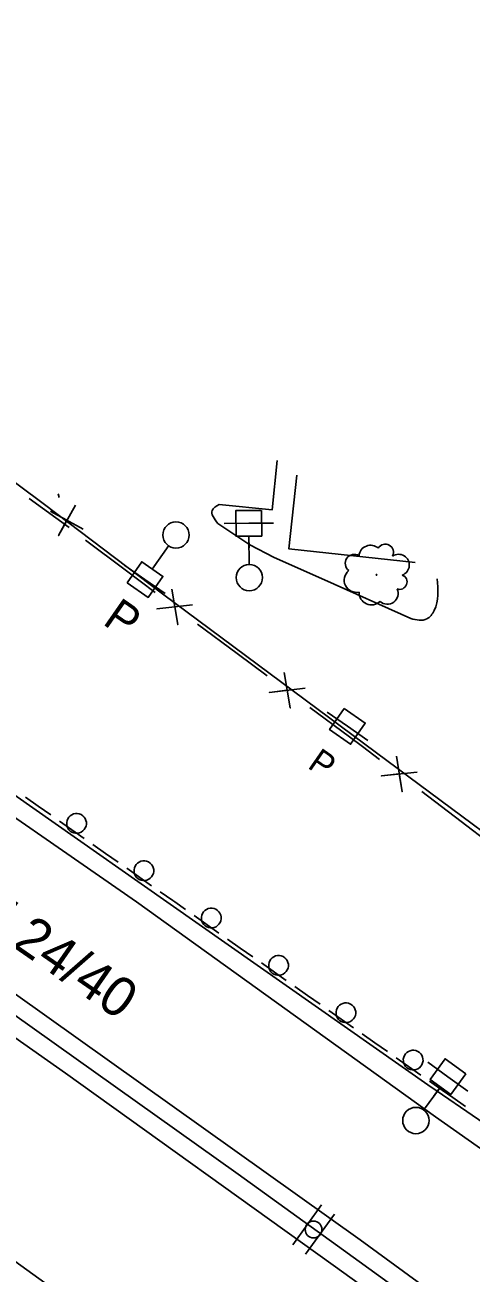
# Model space of a CAD drawing. Extents: x 1746010 to 1754829, y 655801 to 663091.
# Drawn here: x 1747943.2 to 1748078.7, y 661903.4 to 662282.7 of the extents above; entities that cross this region are included whole.
import ezdxf

# ---------------------------------------------------------------- set-up
doc = ezdxf.new("R2010")
doc.units = 0
for name, color, linetype in [('SURVEY - AERIAL SURVEY - Photo Control - Points - Locators', 7, 'Continuous'), ('SURVEY - AERIAL SURVEY - Photo Control - Points - Numbers', 7, 'Continuous'), ('SURVEY - AERIAL SURVEY - Photo Control with Text', 7, 'Continuous'), ('SURVEY - CENTERLINE - Existing Roads - Development', 7, 'Continuous'), ('SURVEY - CENTERLINE - Existing Roads Curve Text', 7, 'Continuous'), ('SURVEY - CENTERLINE - Existing Roads Text', 7, 'Continuous'), ('SURVEY - CONTROL - Points - Numbers', 7, 'Continuous')]:
    doc.layers.add(name, color=color, linetype=linetype)

msp = doc.modelspace()

# ---------------------------------------------------------------- linework, layer by layer
at = {"layer": 'SURVEY - AERIAL SURVEY - Photo Control - Points - Locators'}
for points in [[(1748066.62, 661959.87), (1747978.51, 662021.63), (1747901.08, 662075.95), (1747819.42, 662131.94), (1747745.85, 662180.6), (1747671.72, 662228.98), (1747613.87, 662265.2), (1747545.13, 662307.66)], [(1748067.96, 661950.85), (1747977.15, 662016.22), (1747914.56, 662059.52), (1747827.89, 662119.16), (1747755.21, 662167.87), (1747663.67, 662226.9), (1747617.46, 662256.37), (1747540.61, 662304.67)], [(1747500.14, 662277.89), (1747606.38, 662211.23), (1747699.06, 662151.4), (1747807.18, 662080.79), (1747921.23, 662001.72), (1748045.01, 661913.44)], [(1748036.84, 661905.72), (1747955.58, 661964.08), (1747865.84, 662027.24), (1747772.62, 662090.53), (1747673.46, 662156.1), (1747599.02, 662204.01), (1747520.15, 662254.13), (1747491.6, 662272.24)], [(1747449.54, 662244.42), (1747495.25, 662212.96), (1747544.44, 662177.78), (1747597.81, 662139.99), (1747646.37, 662106.97), (1747700.87, 662070.9), (1747757.2, 662033.9), (1747810.92, 661997.83), (1747873.88, 661953.8), (1747937.26, 661909.07), (1748007.34, 661858.36)], [(1748111.68, 662015.71), (1748050.02, 662061.42), (1747985, 662109.76), (1747949.2, 662136.91), (1747907.89, 662167.74), (1747885.82, 662191.19), (1747883.71, 662193.54), (1747886.26, 662211.22)], [(1748019.82, 662150.29), (1748018.33, 662135.33), (1748002.26, 662136.96)], [(1748001.84, 662131.15), (1748011.52, 662124.73), (1748018.95, 662120.86), (1748034.2, 662114.04), (1748060.39, 662102.28)], [(1748066.45, 661959.99), (1748109.91, 661930.15), (1748120.64, 661926.51), (1748137.02, 661919.36), (1748159.55, 661905.27), (1748212.25, 661870.14), (1748268.84, 661829.36), (1748322.43, 661791.33)], [(1748101.4, 661927.2), (1748067.96, 661950.85)], [(1748045.01, 661913.44), (1748151.1, 661835.82), (1748236.85, 661771.36), (1748316.51, 661710.36), (1748390.54, 661652.24)], [(1749014.37, 661130.26), (1748990.7, 661149.54), (1748916.31, 661209.97), (1748835.38, 661275.76), (1748731.71, 661360.72), (1748655.6, 661422.38), (1748555.07, 661504.4), (1748459.33, 661582.61), (1748380.29, 661646.59), (1748288.83, 661717.68), (1748181.12, 661800.02), (1748091.36, 661866.45), (1748036.84, 661905.72)]]:
    msp.add_lwpolyline(points, dxfattribs=at)
for points in [[(1748002.26, 662136.96), (1748000.05, 662135.17), (1748001.84, 662131.15)], [(1748060.39, 662102.28), (1748065.28, 662102.16), (1748067.5, 662104.72), (1748068.41, 662114.36)]]:
    msp.add_spline(points, degree=3, dxfattribs=at)
at = {"layer": 'SURVEY - AERIAL SURVEY - Photo Control - Points - Numbers'}
for points in [[(1747495.88, 662275.08), (1747565, 662231.38), (1747654.17, 662174.84), (1747729.86, 662125.51), (1747795.86, 662081.53), (1747865.54, 662033.9), (1747933.39, 661986.48), (1748007.95, 661933.43), (1748040.01, 661910.33)], [(1747947.24, 662045.28), (1747943.4, 662047.98)], [(1747951.09, 662042.58), (1747947.24, 662045.28)], [(1747961.24, 662035.45), (1747953.71, 662040.74)], [(1747967.7, 662030.91), (1747963.85, 662033.61)], [(1747971.54, 662028.21), (1747967.7, 662030.91)], [(1747981.69, 662021.08), (1747974.16, 662026.37)], [(1747988.15, 662016.54), (1747984.31, 662019.24)], [(1747992, 662013.83), (1747988.7, 662016.16), (1747988.15, 662016.54)], [(1748002.13, 662006.69), (1747994.61, 662011.99)], [(1748008.59, 662002.14), (1748004.75, 662004.85)], [(1748012.43, 661999.44), (1748008.59, 662002.14)], [(1748022.57, 661992.3), (1748015.05, 661997.59)], [(1748029.03, 661987.75), (1748025.19, 661990.45)], [(1748032.87, 661985.04), (1748029.03, 661987.75)], [(1748043.01, 661977.9), (1748035.49, 661983.2)], [(1748049.47, 661973.35), (1748045.62, 661976.06)], [(1748053.31, 661970.65), (1748049.47, 661973.35)], [(1748063.45, 661963.51), (1748055.93, 661968.8)], [(1748069.91, 661958.96), (1748066.06, 661961.66)], [(1748073.18, 661956.67), (1748069.91, 661958.96)], [(1748077.03, 661953.98), (1748073.18, 661956.67)], [(1748040.01, 661910.33), (1748122.02, 661850.78), (1748195.38, 661796.53), (1748267.56, 661741.32), (1748333.52, 661690.82), (1748402.34, 661636.08), (1748451.04, 661597.23), (1748504.04, 661553.85), (1748559.78, 661508.8), (1748636.39, 661445.77), (1748709.27, 661386.44), (1748757.29, 661347.34), (1748822.35, 661294.7), (1748882.58, 661246), (1748955.33, 661186.03), (1749015.15, 661137.9)]]:
    msp.add_lwpolyline(points, dxfattribs=at)
for centre, start, end in [((1747958.9, 662040.03), 343.8574, 343.8435), ((1747979.36, 662025.65), 343.8574, 343.8435), ((1747999.82, 662011.26), 343.7713, 343.7573), ((1748020.25, 661996.87), 343.7713, 343.7573), ((1748040.69, 661982.47), 343.7713, 343.7573), ((1748061.13, 661968.08), 343.7713, 343.7573)]:
    msp.add_arc(centre, 3, start, end, dxfattribs=at)
at = {"layer": 'SURVEY - AERIAL SURVEY - Photo Control with Text'}
for p, q in [((1748024.54, 661911.92), (1748033.33, 661924.08)), ((1748028.43, 661909.11), (1748037.22, 661921.27))]:
    msp.add_line(p, q, dxfattribs=at)
msp.add_circle((1748030.88, 661916.59), 2.54, dxfattribs=at)
at = {"layer": 'SURVEY - CENTERLINE - Existing Roads - Development'}
for points in [[(1748061.75, 662119.29), (1748023.37, 662123.45), (1748025.8, 662145.87)], [(1747956.62, 662129.94), (1747944.53, 662138.82)], [(1747953.67, 662139.03), (1747953.3, 662140.18)], [(1747960.93, 662129.41), (1747951.09, 662134.84), (1747955.99, 662132.18), (1747953.47, 662127.5), (1747958.55, 662136.75)], [(1747973.64, 662117.1), (1747961.66, 662126.13)], [(1747982.74, 662110.23), (1747973.64, 662117.1)], [(1747994.16, 662106.44), (1747983.32, 662105.2), (1747988.7, 662105.85), (1747989.63, 662100.44), (1747987.85, 662111.2)], [(1748007.66, 662091.63), (1747995.61, 662100.56)], [(1748016.82, 662084.84), (1748007.66, 662091.63)], [(1748028.28, 662081.15), (1748017.45, 662079.82), (1748022.82, 662080.51), (1748023.8, 662075.11), (1748021.93, 662085.85)], [(1748041.81, 662066.33), (1748029.76, 662075.26)], [(1748050.92, 662059.47), (1748045.73, 662063.42), (1748041.81, 662066.33)], [(1748062.33, 662055.62), (1748051.48, 662054.44), (1748056.86, 662055.06), (1748057.76, 662049.65), (1748056.04, 662060.41)], [(1748075.66, 662040.63), (1748063.73, 662049.71)], [(1748084.73, 662033.72), (1748075.66, 662040.63)]]:
    msp.add_lwpolyline(points, dxfattribs=at)
at = {"layer": 'SURVEY - CENTERLINE - Existing Roads Curve Text'}
for p, q in [((1748011.21, 662131.23), (1748003.71, 662131.16)), ((1748011.21, 662131.23), (1748018.71, 662131.3)), ((1748011.33, 662118.63), (1748011.25, 662127.33)), ((1748011.25, 662126.93), (1748011.28, 662123.73)), ((1747986.88, 662124.48), (1747981.91, 662117.34)), ((1747982.14, 662117.67), (1747983.96, 662120.29)), ((1747979.68, 662114.14), (1747973.52, 662118.42)), ((1747979.68, 662114.14), (1747985.84, 662109.85)), ((1748041.16, 662069.54), (1748035.01, 662073.82)), ((1748041.16, 662069.54), (1748047.32, 662065.25)), ((1748071.69, 661963.03), (1748065.63, 661967.46)), ((1748064.26, 661952.86), (1748069.39, 661959.88)), ((1748071.69, 661963.03), (1748077.74, 661958.61)), ((1748069.15, 661959.56), (1748067.26, 661956.98))]:
    msp.add_line(p, q, dxfattribs=at)
for points in [[(1748015.07, 662135.17), (1748015.15, 662127.37), (1748007.35, 662127.29), (1748007.27, 662135.09)], [(1747974.25, 662113.16), (1747978.71, 662119.57), (1747985.11, 662115.11), (1747980.66, 662108.71)], [(1748040.19, 662074.96), (1748046.59, 662070.51), (1748042.14, 662064.1), (1748035.73, 662068.56)], [(1748077.14, 661963.88), (1748072.54, 661957.58), (1748066.24, 661962.18), (1748070.84, 661968.48)]]:
    msp.add_lwpolyline(points, close=True, dxfattribs=at)
for centre in [(1747989.1, 662127.68), (1748011.37, 662114.73), (1748061.95, 661949.71)]:
    msp.add_circle(centre, 4, dxfattribs=at)
at = {"layer": 'SURVEY - CENTERLINE - Existing Roads Text'}
msp.add_circle((1748049.99, 662115.58), 0.114, dxfattribs=at)
for centre, radius, start, end in [((1748048.19, 662121.05), 3.52, 47.966, 174.8117), ((1748052.69, 662122.43), 2.48, 332.679, 149.9981), ((1748043.24, 662119.05), 2.73, 58.125, 233.1252), ((1748056.7, 662118.56), 3.26, 290.0603, 123.48), ((1748043.87, 662113.94), 3.7, 127.8721, 283.7105), ((1748057.01, 662113.4), 2.25, 250.0396, 68.7853), ((1748048.47, 662110.15), 3.73, 176.9762, 314.5005), ((1748053.27, 662109.92), 3.27, 227.9235, 24.7124)]:
    msp.add_arc(centre, radius, start, end, dxfattribs=at)

# ---------------------------------------------------------------- texts
at = {"layer": 'SURVEY - CENTERLINE - Existing Roads Curve Text'}
for height, p in [(10, (1747966.49, 662100.78)), (7.48, (1748028.74, 662057.1))]:
    msp.add_text('P', height=height, rotation=325.1729, dxfattribs=at).set_placement(p)
at = {"layer": 'SURVEY - CONTROL - Points - Numbers'}
msp.add_text('INTERSTATE 24/40', height=12, rotation=325.269, dxfattribs=at).set_placement((1747853.16, 662062.3))

doc.saveas('drawing.dxf')
